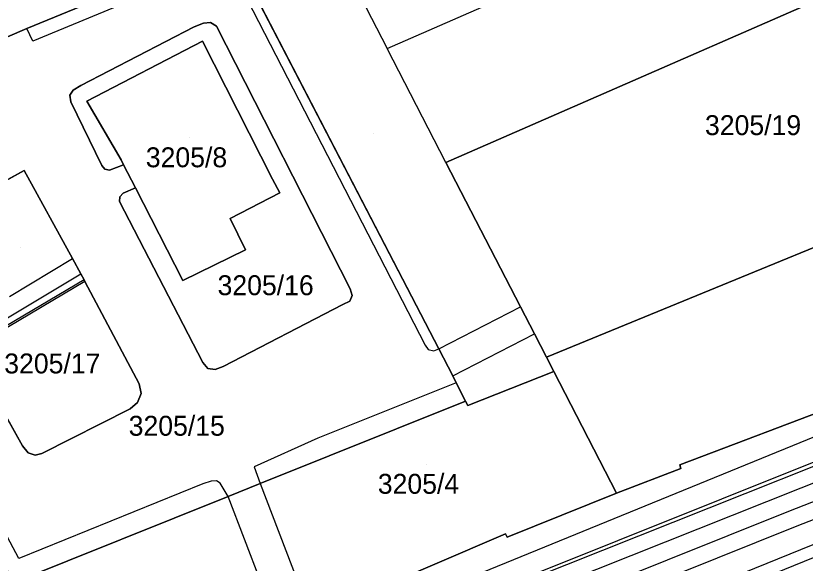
# Model space of a CAD drawing. Extents: x -264070 to -262271, y -1238894 to -1238141.
# Drawn here: x -262992.9 to -262913.5, y -1238698.8 to -1238643.9 of the extents above; entities that cross this region are included whole.
import ezdxf

# ---------------------------------------------------------------- set-up
doc = ezdxf.new("R2010")
doc.units = 0
for name, color, linetype in [('body_kn', 7, 'Continuous'), ('kladpar_druhypozemkov', 7, 'Continuous'), ('kladpar_hranice', 7, 'Continuous'), ('kladpar_parcelnecisla', 7, 'Continuous'), ('kladpar_plochy', 7, 'Continuous'), ('tarchy_linie', 7, 'Continuous'), ('zappar_hrandruhpozemk', 7, 'Continuous')]:
    doc.layers.add(name, color=color, linetype=linetype)

msp = doc.modelspace()

# ---------------------------------------------------------------- linework, layer by layer
at = {"layer": 'body_kn'}
for p, q in [((-262973.29, -1238644.52), (-262973.29, -1238644.52)), ((-262991.75, -1238645.12), (-262991.75, -1238645.12)), ((-262974.93, -1238644.97), (-262974.93, -1238644.97)), ((-262974, -1238644.58), (-262974, -1238644.58)), ((-262972.69, -1238644.91), (-262972.69, -1238644.91)), ((-262991.16, -1238646.41), (-262991.16, -1238646.41)), ((-262974.09, -1238646.42), (-262974.09, -1238646.42)), ((-262974.09, -1238646.42), (-262974.09, -1238646.42)), ((-262955.55, -1238647.13), (-262955.55, -1238647.13)), ((-262955.55, -1238647.13), (-262955.55, -1238647.13)), ((-262986.33, -1238650.86), (-262986.33, -1238650.86)), ((-262987.11, -1238651.34), (-262987.11, -1238651.34)), ((-262987.44, -1238651.83), (-262987.44, -1238651.83)), ((-262985.73, -1238652.42), (-262985.73, -1238652.42)), ((-262987.35, -1238652.5), (-262987.35, -1238652.5)), ((-262982.29, -1238658.32), (-262982.29, -1238658.32)), ((-262949.65, -1238658.59), (-262949.65, -1238658.59)), ((-262949.65, -1238658.59), (-262949.65, -1238658.59)), ((-262992.04, -1238659.39), (-262992.04, -1238659.39)), ((-262984.21, -1238658.88), (-262984.21, -1238658.88)), ((-262983.91, -1238659.27), (-262983.91, -1238659.27)), ((-262983.46, -1238659.37), (-262983.46, -1238659.37)), ((-262982.03, -1238658.83), (-262982.03, -1238658.83)), ((-262967.06, -1238660.26), (-262967.06, -1238660.26)), ((-262980.85, -1238661.13), (-262980.85, -1238661.13)), ((-262982.09, -1238661.66), (-262982.09, -1238661.66)), ((-262966.34, -1238661.65), (-262966.34, -1238661.65)), ((-262982.44, -1238662.52), (-262982.44, -1238662.52)), ((-262982.42, -1238662.03), (-262982.42, -1238662.03)), ((-262971.31, -1238664.21), (-262971.31, -1238664.21)), ((-262969.77, -1238667.36), (-262969.77, -1238667.36)), ((-262987.16, -1238668.24), (-262987.16, -1238668.24)), ((-262986.33, -1238669.78), (-262986.33, -1238669.78)), ((-262986, -1238670.39), (-262986, -1238670.39)), ((-262986, -1238670.39), (-262986, -1238670.39)), ((-262985.92, -1238670.53), (-262985.92, -1238670.53)), ((-262985.92, -1238670.53), (-262985.92, -1238670.53)), ((-262976.09, -1238670.46), (-262976.09, -1238670.46)), ((-262959.24, -1238671.29), (-262959.24, -1238671.29)), ((-262959.06, -1238671.96), (-262959.06, -1238671.96)), ((-262959.98, -1238672.86), (-262959.98, -1238672.86)), ((-262959.29, -1238672.51), (-262959.29, -1238672.51)), ((-262942.14, -1238673.1), (-262942.14, -1238673.1)), ((-262940.73, -1238675.81), (-262940.73, -1238675.81)), ((-262951.72, -1238676.93), (-262951.72, -1238676.93)), ((-262951.4, -1238677.39), (-262951.4, -1238677.39)), ((-262950.84, -1238677.51), (-262950.84, -1238677.51)), ((-262950.35, -1238677.31), (-262950.35, -1238677.31)), ((-262950.35, -1238677.31), (-262950.35, -1238677.31)), ((-262939.53, -1238678.14), (-262939.53, -1238678.14)), ((-262974.05, -1238678.69), (-262974.05, -1238678.69)), ((-262973.56, -1238679.27), (-262973.56, -1238679.27)), ((-262972.81, -1238679.37), (-262972.81, -1238679.37)), ((-262972.02, -1238679.08), (-262972.02, -1238679.08)), ((-262948.95, -1238680.03), (-262948.95, -1238680.03)), ((-262948.95, -1238680.03), (-262948.95, -1238680.03)), ((-262938.79, -1238679.58), (-262938.79, -1238679.58)), ((-262980.46, -1238680.82), (-262980.46, -1238680.82)), ((-262948.59, -1238680.74), (-262948.59, -1238680.74)), ((-262948.59, -1238680.74), (-262948.59, -1238680.74)), ((-262980.27, -1238681.79), (-262980.27, -1238681.79)), ((-262947.65, -1238682.57), (-262947.65, -1238682.57)), ((-262947.65, -1238682.57), (-262947.65, -1238682.57)), ((-262981.38, -1238683.33), (-262981.38, -1238683.33)), ((-262980.64, -1238682.7), (-262980.64, -1238682.7)), ((-262947.42, -1238683.01), (-262947.42, -1238683.01)), ((-262962.52, -1238686.3), (-262962.52, -1238686.3)), ((-262992.18, -1238687.04), (-262992.18, -1238687.04)), ((-262991.64, -1238687.76), (-262991.64, -1238687.76)), ((-262990.93, -1238688), (-262990.93, -1238688)), ((-262990.26, -1238687.81), (-262990.26, -1238687.81)), ((-262926.12, -1238688.97), (-262926.12, -1238688.97)), ((-262968.91, -1238689.18), (-262968.91, -1238689.18)), ((-262926.02, -1238689.32), (-262926.02, -1238689.32)), ((-262974.05, -1238690.87), (-262974.05, -1238690.87)), ((-262973.24, -1238690.59), (-262973.24, -1238690.59)), ((-262972.69, -1238690.56), (-262972.69, -1238690.56)), ((-262972.33, -1238690.81), (-262972.33, -1238690.81)), ((-262968.3, -1238690.84), (-262968.3, -1238690.84)), ((-262968.3, -1238690.84), (-262968.3, -1238690.84)), ((-262971.51, -1238692.13), (-262971.51, -1238692.13)), ((-262971.51, -1238692.13), (-262971.51, -1238692.13)), ((-262932.47, -1238691.8), (-262932.47, -1238691.8)), ((-262915.16, -1238693.61), (-262915.16, -1238693.61)), ((-262914.53, -1238695.19), (-262914.53, -1238695.19)), ((-262943.63, -1238695.89), (-262943.63, -1238695.89)), ((-262943.63, -1238695.89), (-262943.63, -1238695.89)), ((-262943.46, -1238696.23), (-262943.46, -1238696.23)), ((-262992.58, -1238698.36), (-262992.58, -1238698.36))]:
    msp.add_line(p, q, dxfattribs=at)
at = {"layer": 'kladpar_druhypozemkov'}
for p, q in [((-262918.06, -1238654.04), (-262918.06, -1238654.04)), ((-262975.45, -1238656.07), (-262975.45, -1238656.07)), ((-262956.93, -1238655.72), (-262956.93, -1238655.72)), ((-262992.37, -1238667.13), (-262992.37, -1238667.13)), ((-262967.06, -1238670.12), (-262967.06, -1238670.12)), ((-262988.5, -1238678.05), (-262988.5, -1238678.05)), ((-262975.94, -1238684.24), (-262975.94, -1238684.24)), ((-262951.55, -1238688.97), (-262951.55, -1238688.97))]:
    msp.add_line(p, q, dxfattribs=at)
at = {"layer": 'kladpar_hranice'}
for points in [[(-262896.4, -1238635.32), (-262949.65, -1238658.59), (-262942.14, -1238673.1), (-262940.73, -1238675.81), (-262939.53, -1238678.14), (-262938.79, -1238679.58), (-262947.42, -1238683.01), (-262947.65, -1238682.57), (-262948.59, -1238680.74), (-262948.95, -1238680.03), (-262950.35, -1238677.31), (-262968.79, -1238641.75), (-262969.81, -1238639.74), (-262971.32, -1238636.73), (-262962.63, -1238633.33), (-262969.23, -1238620.88), (-262949.83, -1238613.04)], [(-262978.2, -1238622.99), (-262971.32, -1238636.73), (-262991.75, -1238645.12), (-262993.71, -1238645.98), (-262994.92, -1238646.51), (-262996.13, -1238647.01), (-262997.81, -1238647.72), (-262999.1, -1238648.26), (-263016.81, -1238655.62), (-263017.48, -1238655.9), (-263020.39, -1238657.1), (-263023.76, -1238649.66), (-263026.91, -1238643.19), (-263003.89, -1238633.64), (-263000.97, -1238632.43), (-262996.2, -1238630.39), (-262993.97, -1238629.43), (-262978.2, -1238622.99)], [(-262896.4, -1238635.32), (-262893.51, -1238640.81), (-262897.88, -1238642.99), (-262896.12, -1238646.52), (-262895.71, -1238646.31), (-262889.69, -1238657.71), (-262939.53, -1238678.14), (-262940.73, -1238675.81), (-262942.14, -1238673.1), (-262949.65, -1238658.59), (-262896.4, -1238635.32)], [(-262997.81, -1238647.72), (-262996.13, -1238647.01), (-262994.92, -1238646.51), (-262993.71, -1238645.98), (-262991.75, -1238645.12), (-262971.32, -1238636.73), (-262969.81, -1238639.74), (-262968.79, -1238641.75), (-262950.35, -1238677.31), (-262948.95, -1238680.03), (-262948.59, -1238680.74), (-262947.65, -1238682.57), (-262968.3, -1238690.84), (-262971.51, -1238692.13), (-262993.08, -1238700.78), (-263010.47, -1238667.87), (-263016.81, -1238655.62), (-262999.1, -1238648.26), (-262997.81, -1238647.72)], [(-262880.12, -1238640.03), (-262869.99, -1238667.58), (-262878.72, -1238670.99), (-262878.93, -1238670.68), (-262894.75, -1238676.83), (-262894.63, -1238677.26), (-262909.38, -1238683.08), (-262909.66, -1238682.73), (-262926.12, -1238688.97), (-262926.02, -1238689.32), (-262932.47, -1238691.8), (-262938.79, -1238679.58), (-262939.53, -1238678.14), (-262889.69, -1238657.71), (-262895.71, -1238646.31), (-262891.67, -1238644.28), (-262880.12, -1238640.03)], [(-262974.09, -1238646.42), (-262985.73, -1238652.42), (-262982.29, -1238658.32), (-262982.03, -1238658.83), (-262983.46, -1238659.37), (-262983.91, -1238659.27), (-262984.21, -1238658.88), (-262987.35, -1238652.5), (-262987.44, -1238651.83), (-262987.11, -1238651.34), (-262986.33, -1238650.86), (-262974.93, -1238644.97), (-262974, -1238644.58), (-262973.29, -1238644.52), (-262972.69, -1238644.91), (-262959.24, -1238671.29), (-262959.06, -1238671.96), (-262959.29, -1238672.51), (-262959.98, -1238672.86), (-262972.02, -1238679.08), (-262972.81, -1238679.37), (-262973.56, -1238679.27), (-262974.05, -1238678.69), (-262982.44, -1238662.52), (-262982.42, -1238662.03), (-262982.09, -1238661.66), (-262980.85, -1238661.13), (-262976.09, -1238670.46), (-262969.77, -1238667.36), (-262971.31, -1238664.21), (-262966.34, -1238661.65), (-262967.06, -1238660.26), (-262974.09, -1238646.42)], [(-262983.46, -1238659.37), (-262982.03, -1238658.83), (-262980.85, -1238661.13), (-262982.09, -1238661.66), (-262982.42, -1238662.03), (-262982.44, -1238662.52), (-262974.05, -1238678.69), (-262973.56, -1238679.27), (-262972.81, -1238679.37), (-262972.02, -1238679.08), (-262959.98, -1238672.86), (-262959.29, -1238672.51), (-262959.06, -1238671.96), (-262959.24, -1238671.29), (-262972.69, -1238644.91), (-262973.29, -1238644.52), (-262974, -1238644.58), (-262974.93, -1238644.97), (-262986.33, -1238650.86), (-262987.11, -1238651.34), (-262987.44, -1238651.83), (-262987.35, -1238652.5), (-262984.21, -1238658.88), (-262983.91, -1238659.27), (-262983.46, -1238659.37)], [(-262974.09, -1238646.42), (-262967.06, -1238660.26), (-262966.34, -1238661.65), (-262971.31, -1238664.21), (-262969.77, -1238667.36), (-262976.09, -1238670.46), (-262980.85, -1238661.13), (-262982.03, -1238658.83), (-262982.29, -1238658.32), (-262985.73, -1238652.42), (-262974.09, -1238646.42)], [(-262997.26, -1238662.26), (-262992.04, -1238659.39), (-262987.16, -1238668.24), (-262986.33, -1238669.78), (-262986, -1238670.39), (-262985.92, -1238670.53), (-262980.46, -1238680.82), (-262980.27, -1238681.79), (-262980.64, -1238682.7), (-262981.38, -1238683.33), (-262990.26, -1238687.81), (-262990.93, -1238688), (-262991.64, -1238687.76), (-262992.18, -1238687.04), (-262996.09, -1238680.14)], [(-262996.09, -1238680.14), (-262992.18, -1238687.04), (-262991.64, -1238687.76), (-262990.93, -1238688), (-262990.26, -1238687.81), (-262981.38, -1238683.33), (-262980.64, -1238682.7), (-262980.27, -1238681.79), (-262980.46, -1238680.82), (-262985.92, -1238670.53), (-262986, -1238670.39), (-262986.33, -1238669.78), (-262987.16, -1238668.24), (-262992.04, -1238659.39), (-262997.26, -1238662.26)], [(-262947.65, -1238682.57), (-262947.42, -1238683.01), (-262938.79, -1238679.58), (-262932.47, -1238691.8), (-262943.46, -1238696.23), (-262943.63, -1238695.89), (-262958.07, -1238702.1), (-262957.95, -1238702.43), (-262963.07, -1238704.47), (-262963.54, -1238704.66), (-262966.3, -1238705.75), (-262972.26, -1238708.2), (-262972.41, -1238707.87), (-262987.6, -1238713.86), (-262987.53, -1238714.09), (-262996.41, -1238717.63), (-263002.72, -1238704.48), (-262993.08, -1238700.78), (-262971.51, -1238692.13), (-262968.3, -1238690.84), (-262947.65, -1238682.57)], [(-262943.63, -1238695.89), (-262943.46, -1238696.23), (-262932.47, -1238691.8), (-262926.02, -1238689.32), (-262926.12, -1238688.97), (-262909.66, -1238682.73)], [(-262996.41, -1238717.63), (-262987.53, -1238714.09), (-262987.6, -1238713.86), (-262972.41, -1238707.87), (-262972.26, -1238708.2), (-262966.3, -1238705.75), (-262963.54, -1238704.66), (-262963.07, -1238704.47), (-262957.95, -1238702.43), (-262958.07, -1238702.1), (-262943.63, -1238695.89)]]:
    msp.add_lwpolyline(points, dxfattribs=at)
at = {"layer": 'kladpar_plochy'}
for p, q in [((-262991.75, -1238645.12), (-262971.32, -1238636.73)), ((-262968.79, -1238641.75), (-262950.35, -1238677.31)), ((-262973.29, -1238644.52), (-262974, -1238644.58)), ((-262972.69, -1238644.91), (-262973.29, -1238644.52)), ((-262993.71, -1238645.98), (-262991.75, -1238645.12)), ((-262974.93, -1238644.97), (-262986.33, -1238650.86)), ((-262974, -1238644.58), (-262974.93, -1238644.97)), ((-262959.24, -1238671.29), (-262972.69, -1238644.91)), ((-262986.33, -1238650.86), (-262987.11, -1238651.34)), ((-262987.11, -1238651.34), (-262987.44, -1238651.83)), ((-262987.44, -1238651.83), (-262987.35, -1238652.5)), ((-262987.35, -1238652.5), (-262984.21, -1238658.88)), ((-262992.04, -1238659.39), (-262997.26, -1238662.26)), ((-262987.16, -1238668.24), (-262992.04, -1238659.39)), ((-262984.21, -1238658.88), (-262983.91, -1238659.27)), ((-262983.91, -1238659.27), (-262983.46, -1238659.37)), ((-262983.46, -1238659.37), (-262982.03, -1238658.83)), ((-262982.03, -1238658.83), (-262980.85, -1238661.13)), ((-262980.85, -1238661.13), (-262982.09, -1238661.66)), ((-262982.09, -1238661.66), (-262982.42, -1238662.03)), ((-262982.42, -1238662.03), (-262982.44, -1238662.52)), ((-262982.44, -1238662.52), (-262974.05, -1238678.69)), ((-262986.33, -1238669.78), (-262987.16, -1238668.24)), ((-262986, -1238670.39), (-262986.33, -1238669.78)), ((-262985.92, -1238670.53), (-262986, -1238670.39)), ((-262980.46, -1238680.82), (-262985.92, -1238670.53)), ((-262959.06, -1238671.96), (-262959.24, -1238671.29)), ((-262959.29, -1238672.51), (-262959.06, -1238671.96)), ((-262972.02, -1238679.08), (-262959.98, -1238672.86)), ((-262959.98, -1238672.86), (-262959.29, -1238672.51)), ((-262950.35, -1238677.31), (-262948.95, -1238680.03)), ((-262974.05, -1238678.69), (-262973.56, -1238679.27)), ((-262973.56, -1238679.27), (-262972.81, -1238679.37)), ((-262972.81, -1238679.37), (-262972.02, -1238679.08)), ((-262996.09, -1238680.14), (-262992.18, -1238687.04)), ((-262948.95, -1238680.03), (-262948.59, -1238680.74)), ((-262980.27, -1238681.79), (-262980.46, -1238680.82)), ((-262948.59, -1238680.74), (-262947.65, -1238682.57)), ((-262980.64, -1238682.7), (-262980.27, -1238681.79)), ((-262947.65, -1238682.57), (-262968.3, -1238690.84)), ((-262990.26, -1238687.81), (-262981.38, -1238683.33)), ((-262981.38, -1238683.33), (-262980.64, -1238682.7)), ((-262992.18, -1238687.04), (-262991.64, -1238687.76)), ((-262991.64, -1238687.76), (-262990.93, -1238688)), ((-262990.93, -1238688), (-262990.26, -1238687.81)), ((-262968.3, -1238690.84), (-262971.51, -1238692.13)), ((-262971.51, -1238692.13), (-262993.08, -1238700.78))]:
    msp.add_line(p, q, dxfattribs=at)
for points in [[(-262896.4, -1238635.32), (-262949.65, -1238658.59), (-262942.14, -1238673.1), (-262940.73, -1238675.81), (-262939.53, -1238678.14), (-262938.79, -1238679.58), (-262947.42, -1238683.01), (-262947.65, -1238682.57), (-262948.59, -1238680.74), (-262948.95, -1238680.03), (-262950.35, -1238677.31), (-262968.79, -1238641.75), (-262969.81, -1238639.74), (-262971.32, -1238636.73), (-262962.63, -1238633.33), (-262969.23, -1238620.88), (-262949.83, -1238613.04)], [(-262997.26, -1238662.26), (-262992.04, -1238659.39), (-262987.16, -1238668.24), (-262986.33, -1238669.78), (-262986, -1238670.39), (-262985.92, -1238670.53), (-262980.46, -1238680.82), (-262980.27, -1238681.79), (-262980.64, -1238682.7), (-262981.38, -1238683.33), (-262990.26, -1238687.81), (-262990.93, -1238688), (-262991.64, -1238687.76), (-262992.18, -1238687.04), (-262996.09, -1238680.14)], [(-262996.41, -1238717.63), (-262987.53, -1238714.09), (-262987.6, -1238713.86), (-262972.41, -1238707.87), (-262972.26, -1238708.2), (-262966.3, -1238705.75), (-262963.54, -1238704.66), (-262963.07, -1238704.47), (-262957.95, -1238702.43), (-262958.07, -1238702.1), (-262943.63, -1238695.89), (-262943.46, -1238696.23), (-262932.47, -1238691.8), (-262926.02, -1238689.32), (-262926.12, -1238688.97), (-262909.66, -1238682.73)]]:
    msp.add_lwpolyline(points, dxfattribs=at)
for points in [[(-262978.2, -1238622.99), (-262971.32, -1238636.73), (-262991.75, -1238645.12), (-262993.71, -1238645.98), (-262994.92, -1238646.51), (-262996.13, -1238647.01), (-262997.81, -1238647.72), (-262999.1, -1238648.26), (-263016.81, -1238655.62), (-263017.48, -1238655.9), (-263020.39, -1238657.1), (-263023.76, -1238649.66), (-263026.91, -1238643.19), (-263003.89, -1238633.64), (-263000.97, -1238632.43), (-262996.2, -1238630.39), (-262993.97, -1238629.43)], [(-262896.4, -1238635.32), (-262893.51, -1238640.81), (-262897.88, -1238642.99), (-262896.12, -1238646.52), (-262895.71, -1238646.31), (-262889.69, -1238657.71), (-262939.53, -1238678.14), (-262940.73, -1238675.81), (-262942.14, -1238673.1), (-262949.65, -1238658.59)], [(-262880.12, -1238640.03), (-262869.99, -1238667.58), (-262878.72, -1238670.99), (-262878.93, -1238670.68), (-262894.75, -1238676.83), (-262894.63, -1238677.26), (-262909.38, -1238683.08), (-262909.66, -1238682.73), (-262926.12, -1238688.97), (-262926.02, -1238689.32), (-262932.47, -1238691.8), (-262938.79, -1238679.58), (-262939.53, -1238678.14), (-262889.69, -1238657.71), (-262895.71, -1238646.31), (-262891.67, -1238644.28)], [(-262974.09, -1238646.42), (-262985.73, -1238652.42), (-262982.29, -1238658.32), (-262982.03, -1238658.83), (-262983.46, -1238659.37), (-262983.91, -1238659.27), (-262984.21, -1238658.88), (-262987.35, -1238652.5), (-262987.44, -1238651.83), (-262987.11, -1238651.34), (-262986.33, -1238650.86), (-262974.93, -1238644.97), (-262974, -1238644.58), (-262973.29, -1238644.52), (-262972.69, -1238644.91), (-262959.24, -1238671.29), (-262959.06, -1238671.96), (-262959.29, -1238672.51), (-262959.98, -1238672.86), (-262972.02, -1238679.08), (-262972.81, -1238679.37), (-262973.56, -1238679.27), (-262974.05, -1238678.69), (-262982.44, -1238662.52), (-262982.42, -1238662.03), (-262982.09, -1238661.66), (-262980.85, -1238661.13), (-262976.09, -1238670.46), (-262969.77, -1238667.36), (-262971.31, -1238664.21), (-262966.34, -1238661.65), (-262967.06, -1238660.26)], [(-262974.09, -1238646.42), (-262967.06, -1238660.26), (-262966.34, -1238661.65), (-262971.31, -1238664.21), (-262969.77, -1238667.36), (-262976.09, -1238670.46), (-262980.85, -1238661.13), (-262982.03, -1238658.83), (-262982.29, -1238658.32), (-262985.73, -1238652.42)], [(-262947.65, -1238682.57), (-262947.42, -1238683.01), (-262938.79, -1238679.58), (-262932.47, -1238691.8), (-262943.46, -1238696.23), (-262943.63, -1238695.89), (-262958.07, -1238702.1), (-262957.95, -1238702.43), (-262963.07, -1238704.47), (-262963.54, -1238704.66), (-262966.3, -1238705.75), (-262972.26, -1238708.2), (-262972.41, -1238707.87), (-262987.6, -1238713.86), (-262987.53, -1238714.09), (-262996.41, -1238717.63), (-263002.72, -1238704.48), (-262993.08, -1238700.78), (-262971.51, -1238692.13), (-262968.3, -1238690.84)]]:
    msp.add_lwpolyline(points, close=True, dxfattribs=at)
at = {"layer": 'tarchy_linie'}
for points in [[(-263033.95, -1238737.75), (-263010.93, -1238728.34), (-262962.46, -1238708.92), (-262869.55, -1238671.95), (-262869.38, -1238673.55), (-262869.16, -1238675.64), (-262868.98, -1238677.4), (-262914.53, -1238695.19), (-262969.09, -1238717.08), (-263023.45, -1238739.03), (-263032.54, -1238742.65), (-263033.01, -1238741.01), (-263033.53, -1238739.24), (-263033.92, -1238737.88), (-263033.95, -1238737.75)], [(-263033.53, -1238739.24), (-263010.35, -1238729.78), (-262961.89, -1238710.36), (-262869.38, -1238673.55)], [(-263033.01, -1238741.01), (-263024.08, -1238737.45), (-262969.72, -1238715.5), (-262915.16, -1238693.61), (-262869.16, -1238675.64)]]:
    msp.add_lwpolyline(points, dxfattribs=at)
at = {"layer": 'zappar_hrandruhpozemk'}
for p, q in [((-262962.63, -1238633.33), (-262955.55, -1238647.13)), ((-262971.88, -1238638.4), (-262991.16, -1238646.41)), ((-262969.61, -1238642.18), (-262951.72, -1238676.93)), ((-262955.55, -1238647.13), (-262946.01, -1238643)), ((-262991.16, -1238646.41), (-262991.75, -1238645.12)), ((-262949.65, -1238658.59), (-262955.55, -1238647.13)), ((-262993.51, -1238672.05), (-262987.16, -1238668.24)), ((-262998, -1238676.77), (-262986.33, -1238669.78)), ((-262986, -1238670.39), (-262997.71, -1238677.29)), ((-262985.92, -1238670.53), (-262997.46, -1238677.36)), ((-262950.35, -1238677.31), (-262942.14, -1238673.1)), ((-262948.95, -1238680.03), (-262940.73, -1238675.81)), ((-262963.98, -1238717.73), (-262869.63, -1238679.5)), ((-262868.68, -1238680.43), (-262963.45, -1238718.87)), ((-262948.59, -1238680.74), (-262962.52, -1238686.3)), ((-262963.13, -1238706.75), (-262902.85, -1238682.16)), ((-262901.91, -1238684.38), (-262944.75, -1238701.53)), ((-262968.3, -1238690.84), (-262963.07, -1238704.47)), ((-262966.3, -1238705.75), (-262971.51, -1238692.13))]:
    msp.add_line(p, q, dxfattribs=at)
for points in [[(-262974.05, -1238690.87), (-262992.58, -1238698.36), (-263005.88, -1238673.39)], [(-262951.72, -1238676.93), (-262951.4, -1238677.39), (-262950.84, -1238677.51), (-262950.35, -1238677.31)], [(-262962.52, -1238686.3), (-262968.91, -1238689.18), (-262968.3, -1238690.84)], [(-262971.51, -1238692.13), (-262972.33, -1238690.81), (-262972.69, -1238690.56), (-262973.24, -1238690.59), (-262974.05, -1238690.87)]]:
    msp.add_lwpolyline(points, dxfattribs=at)

# ---------------------------------------------------------------- texts
at = {"layer": 'kladpar_parcelnecisla'}
for s, p in [('3205/19', (-262923.587, -1238655.84)), ('3205/8', (-262979.799, -1238659.07)), ('3205/16', (-262972.587, -1238671.92)), ('3205/17', (-262994.03, -1238679.78)), ('3205/15', (-262981.522, -1238686.04)), ('3205/4', (-262956.476, -1238691.87))]:
    msp.add_text(s, height=2, dxfattribs=at).set_placement(p)

doc.saveas('drawing.dxf')
